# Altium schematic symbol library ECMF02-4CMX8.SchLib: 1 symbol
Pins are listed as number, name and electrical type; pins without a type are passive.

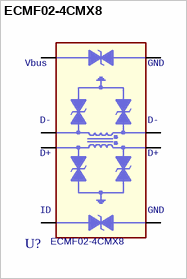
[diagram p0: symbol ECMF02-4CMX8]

## ECMF02-4CMX8
designator U?
footprint ST_QFN50P255X125X55-8L
pins: 1 Vbus, 2 D-, 3 D+, 4 ID, 5 GND, 6 D+1, 7 D-1, 8 GND1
